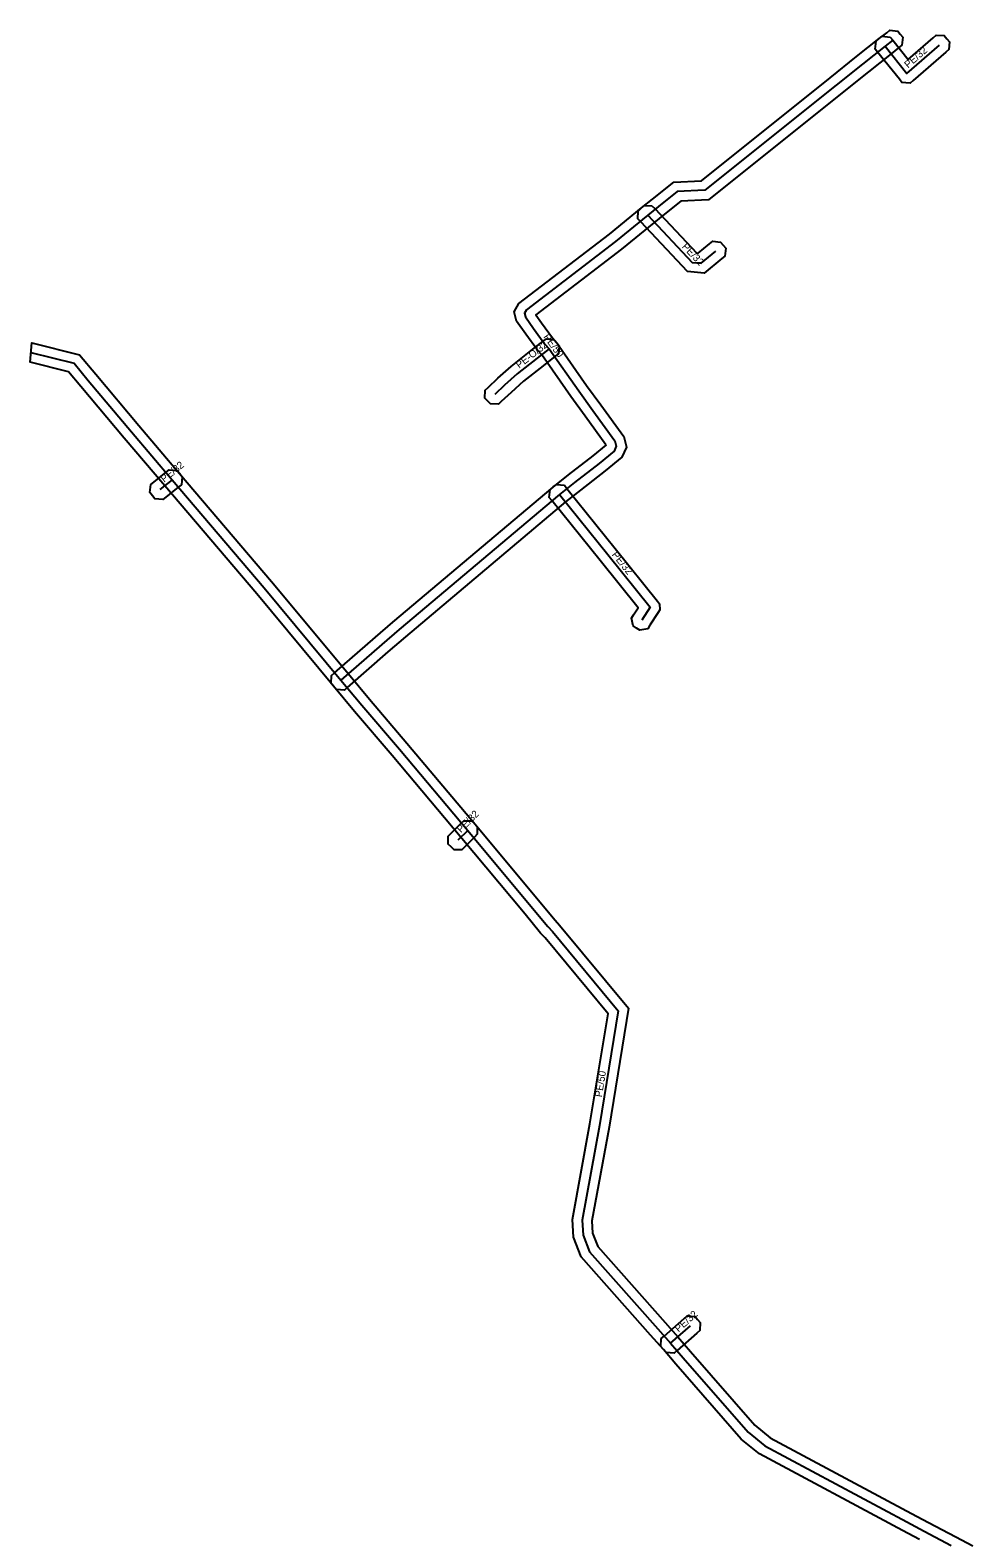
# Model space of a CAD drawing. Extents: x -682697 to -681888, y -1059966 to -1059631.
# Drawn here: x -682696.7 to -682598.9, y -1059809.7 to -1059653.3 of the extents above; entities that cross this region are included whole.
import ezdxf

# ---------------------------------------------------------------- set-up
doc = ezdxf.new("R2010")
doc.units = 0
for name, color, linetype in [('1', 7, 'Continuous'), ('24', 7, 'Continuous'), ('30', 7, 'Continuous')]:
    doc.layers.add(name, color=color, linetype=linetype)

msp = doc.modelspace()

# ---------------------------------------------------------------- linework, layer by layer
at = {"layer": '1'}
for points in [[(-682635.32, -1059675.99), (-682644.21, -1059682.8), (-682643.62, -1059683.63), (-682642.48, -1059685.2), (-682642.03, -1059685.69), (-682638.93, -1059690.12), (-682637.47, -1059692.13), (-682635.08, -1059695.44), (-682634.79, -1059696.53), (-682635.27, -1059697.57), (-682637.01, -1059699), (-682639.57, -1059700.99), (-682641.13, -1059702.22), (-682657.73, -1059716.22), (-682659.54, -1059717.77), (-682663.76, -1059721.46), (-682664.07, -1059721.74), (-682664.9, -1059721.68), (-682665.17, -1059721.37), (-682665.45, -1059721.06), (-682665.39, -1059720.23), (-682665.08, -1059719.96), (-682660.84, -1059716.25), (-682659.03, -1059714.7), (-682642.39, -1059700.67), (-682640.81, -1059699.41), (-682638.25, -1059697.44), (-682636.91, -1059696.34), (-682636.92, -1059696.3), (-682639.09, -1059693.31), (-682640.56, -1059691.28), (-682643.59, -1059686.95), (-682644.04, -1059686.46), (-682645.24, -1059684.79), (-682646.2, -1059683.45), (-682646.45, -1059682.49), (-682645.95, -1059681.61), (-682636.56, -1059674.42), (-682633.22, -1059671.69), (-682632.1, -1059670.79), (-682629.89, -1059669.03), (-682627.02, -1059668.89), (-682613.65, -1059658.2), (-682610.91, -1059656.01), (-682608.57, -1059654.14), (-682607.79, -1059653.52), (-682607.47, -1059653.26), (-682606.65, -1059653.35), (-682606.39, -1059653.68), (-682606.13, -1059654), (-682606.22, -1059654.82), (-682606.55, -1059655.08), (-682607.33, -1059655.7), (-682609.67, -1059657.57), (-682612.41, -1059659.76), (-682626.28, -1059670.85), (-682629.15, -1059670.99), (-682630.84, -1059672.35), (-682631.96, -1059673.25)], [(-682607.43, -1059653.97), (-682607.17, -1059654.3), (-682605.57, -1059656.3), (-682602.96, -1059654.04), (-682602.65, -1059653.77), (-682601.83, -1059653.83), (-682601.56, -1059654.15), (-682601.28, -1059654.46), (-682601.34, -1059655.28), (-682601.66, -1059655.55), (-682605.05, -1059658.5), (-682605.37, -1059658.77), (-682605.79, -1059658.74), (-682606.22, -1059658.7), (-682606.48, -1059658.36), (-682608.73, -1059655.54), (-682608.99, -1059655.22), (-682608.9, -1059654.4), (-682608.57, -1059654.14), (-682608.25, -1059653.88)], [(-682632.15, -1059671.48), (-682631.86, -1059671.78), (-682627.51, -1059676.4), (-682627.36, -1059676.41), (-682626.17, -1059675.43), (-682625.84, -1059675.16), (-682625.02, -1059675.25), (-682624.76, -1059675.56), (-682624.49, -1059675.89), (-682624.58, -1059676.71), (-682624.9, -1059676.97), (-682626.72, -1059678.47), (-682628.45, -1059678.32), (-682633.32, -1059673.16), (-682633.6, -1059672.85), (-682633.58, -1059672.03), (-682633.28, -1059671.74), (-682632.97, -1059671.46)], [(-682641.86, -1059686.85), (-682642.19, -1059687.1), (-682643.43, -1059688.09), (-682645.49, -1059689.69), (-682646.77, -1059690.85), (-682647.79, -1059691.79), (-682648.09, -1059692.07), (-682648.92, -1059692.04), (-682649.2, -1059691.74), (-682649.48, -1059691.44), (-682649.45, -1059690.61), (-682649.15, -1059690.33), (-682648.13, -1059689.37), (-682646.77, -1059688.15), (-682644.67, -1059686.51), (-682643.43, -1059685.53), (-682643.1, -1059685.28), (-682642.28, -1059685.38), (-682642.03, -1059685.7), (-682641.77, -1059686.02)], [(-682680.98, -1059700.43), (-682681.3, -1059700.69), (-682682.58, -1059701.72), (-682682.91, -1059701.98), (-682683.73, -1059701.89), (-682683.99, -1059701.57), (-682684.25, -1059701.24), (-682684.16, -1059700.42), (-682683.84, -1059700.16), (-682682.56, -1059699.13), (-682682.23, -1059698.87), (-682681.41, -1059698.96), (-682681.15, -1059699.28), (-682680.89, -1059699.61)], [(-682641.24, -1059700.49), (-682640.98, -1059700.81), (-682635.96, -1059707.05), (-682631.57, -1059712.52), (-682631.37, -1059712.78), (-682631.33, -1059713.42), (-682631.51, -1059713.69), (-682632.37, -1059715.02), (-682632.59, -1059715.37), (-682633.41, -1059715.54), (-682633.75, -1059715.32), (-682634.1, -1059715.09), (-682634.28, -1059714.28), (-682634.05, -1059713.94), (-682633.58, -1059713.21), (-682637.52, -1059708.31), (-682642.54, -1059702.07), (-682642.8, -1059701.74), (-682642.71, -1059700.92), (-682642.39, -1059700.66), (-682642.06, -1059700.4)], [(-682650.27, -1059736.71), (-682650.56, -1059737.01), (-682651.57, -1059738.02), (-682651.87, -1059738.31), (-682652.69, -1059738.31), (-682652.99, -1059738.02), (-682653.28, -1059737.72), (-682653.28, -1059736.9), (-682652.99, -1059736.6), (-682651.98, -1059735.59), (-682651.68, -1059735.3), (-682650.86, -1059735.3), (-682650.56, -1059735.59), (-682650.27, -1059735.89)], [(-682631.18, -1059789.04), (-682630.87, -1059788.77), (-682628.82, -1059786.96), (-682628.51, -1059786.69), (-682627.68, -1059786.74), (-682627.41, -1059787.05), (-682627.14, -1059787.36), (-682627.19, -1059788.19), (-682627.5, -1059788.46), (-682629.55, -1059790.27), (-682629.86, -1059790.54), (-682630.69, -1059790.49), (-682630.96, -1059790.18), (-682631.23, -1059789.87)]]:
    msp.add_lwpolyline(points, close=True, dxfattribs=at)
msp.add_lwpolyline([(-682604.39, -1059809.89), (-682606.16, -1059808.94), (-682621, -1059801.01), (-682622.88, -1059799.46), (-682629.66, -1059791.69), (-682630.96, -1059790.18), (-682632.29, -1059788.68), (-682639.5, -1059780.55), (-682640.29, -1059778.53), (-682640.4, -1059776.69), (-682638.58, -1059766.76), (-682636.71, -1059755.33), (-682643.23, -1059747.46), (-682643.7, -1059746.95), (-682645.32, -1059745.01), (-682652.04, -1059736.94), (-682659.11, -1059728.54), (-682663.01, -1059723.97), (-682665.19, -1059721.35), (-682673.16, -1059711.76), (-682682.69, -1059700.56), (-682686.9, -1059695.59), (-682691.41, -1059690.24), (-682692.68, -1059688.72), (-682696.67, -1059687.72), (-682696.51, -1059685.7), (-682691.56, -1059686.94), (-682689.87, -1059688.96), (-682685.38, -1059694.3), (-682681.17, -1059699.26), (-682671.62, -1059710.48), (-682663.65, -1059720.07), (-682661.47, -1059722.68), (-682657.59, -1059727.24), (-682650.5, -1059735.66), (-682643.78, -1059743.73), (-682642.2, -1059745.63), (-682641.73, -1059746.14), (-682634.59, -1059754.75), (-682636.6, -1059767.1), (-682638.39, -1059776.81), (-682638.31, -1059778.09), (-682637.76, -1059779.49), (-682630.79, -1059787.36), (-682629.46, -1059788.86), (-682628.15, -1059790.37), (-682621.48, -1059798.02), (-682619.88, -1059799.33), (-682605.22, -1059807.18), (-682603.45, -1059808.13), (-682600.63, -1059809.61), (-682598.85, -1059810.55)], dxfattribs=at)
at = {"layer": '24'}
for points in [[(-682607.17, -1059654.3), (-682607.95, -1059654.92), (-682610.29, -1059656.79), (-682613.03, -1059658.98), (-682626.65, -1059669.87), (-682629.52, -1059670.01), (-682631.47, -1059671.57), (-682632.59, -1059672.47), (-682635.94, -1059675.2), (-682645.18, -1059682.28), (-682645.38, -1059682.63), (-682645.28, -1059683.02), (-682644.43, -1059684.21), (-682643.26, -1059685.83), (-682642.81, -1059686.32), (-682639.74, -1059690.7), (-682638.28, -1059692.72), (-682636, -1059695.87), (-682635.85, -1059696.44), (-682636.08, -1059696.95), (-682637.63, -1059698.22), (-682640.19, -1059700.2), (-682641.76, -1059701.44), (-682658.38, -1059715.46), (-682660.19, -1059717.01), (-682664.42, -1059720.71)], [(-682607.95, -1059654.92), (-682605.7, -1059657.74), (-682602.31, -1059654.8)], [(-682632.59, -1059672.47), (-682627.98, -1059677.36), (-682627.04, -1059677.44), (-682625.53, -1059676.2)], [(-682642.81, -1059686.32), (-682644.05, -1059687.3), (-682646.13, -1059688.92), (-682647.45, -1059690.11), (-682648.47, -1059691.06)], [(-682696.59, -1059686.71), (-682692.12, -1059687.83), (-682690.64, -1059689.6), (-682686.14, -1059694.95), (-682681.93, -1059699.91), (-682672.39, -1059711.12), (-682664.42, -1059720.71), (-682662.24, -1059723.32), (-682658.35, -1059727.89), (-682651.27, -1059736.3), (-682644.55, -1059744.37), (-682642.95, -1059746.29), (-682642.48, -1059746.8), (-682635.65, -1059755.04), (-682637.59, -1059766.93), (-682639.39, -1059776.75), (-682639.3, -1059778.31), (-682638.63, -1059780.02), (-682631.54, -1059788.02), (-682630.21, -1059789.52), (-682628.9, -1059791.03), (-682622.18, -1059798.74), (-682620.44, -1059800.17), (-682605.69, -1059808.06), (-682603.92, -1059809.01), (-682601.09, -1059810.5)], [(-682681.93, -1059699.91), (-682683.21, -1059700.94)], [(-682641.76, -1059701.44), (-682636.74, -1059707.68), (-682632.35, -1059713.15), (-682633.21, -1059714.48)], [(-682651.27, -1059736.3), (-682652.28, -1059737.31)], [(-682630.21, -1059789.52), (-682628.16, -1059787.71)]]:
    msp.add_lwpolyline(points, dxfattribs=at)

# ---------------------------------------------------------------- texts
at = {"layer": '30'}
for s, rotation, p in [('PE/32', 40.9337, (-682605.57, -1059657.25)), ('PE/32', 313.3118, (-682629.09, -1059675.77)), ('PE/50', 305.8377, (-682643.45, -1059685.09)), ('PE-O/32', 37.9131, (-682645.92, -1059688.4)), ('PE/32', 38.8232, (-682682.77, -1059700.23)), ('PE/32', 308.7491, (-682636.36, -1059707.71)), ('PE/32', 45, (-682651.97, -1059736.6)), ('PE/50', 80.7331, (-682637.35, -1059764.02)), ('PE/32', 41.4421, (-682629.39, -1059788.42))]:
    msp.add_text(s, height=0.75, rotation=rotation, dxfattribs=at).set_placement(p)

doc.saveas('drawing.dxf')
